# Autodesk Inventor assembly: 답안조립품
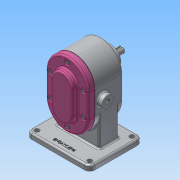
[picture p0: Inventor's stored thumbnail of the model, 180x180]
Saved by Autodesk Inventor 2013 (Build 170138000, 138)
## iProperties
Created: 2020-09
Part Number: 답안조립품
Document SubType Name: Assembly
Designer: Administrator
Author: Administrator
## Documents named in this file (11)
- C:\Users\Administrator\Desktop\700906V1002\답안조립품.iam
- C:\Users\Administrator\Desktop\700906V1002\본체.ipt
- C:\Users\Administrator\Desktop\700906V1002\메인축.ipt
- C:\Users\Administrator\Desktop\700906V1002\베어링부시.ipt
- C:\Users\Administrator\Desktop\700906V1002\스퍼기어.ipt
- C:\Users\Administrator\Desktop\700906V1002\개스킷.ipt
- C:\Users\Administrator\Desktop\700906V1002\키 6 x 6 x 18.ipt
- C:\Users\Administrator\Desktop\700906V1002\커버.ipt
- C:\Users\Administrator\Desktop\700906V1002\서브축.ipt
- C:\Users\Administrator\Desktop\700906V1002\볼트 M5.ipt
- C:\Users\Administrator\Desktop\700906V1002\오일 실 16 28 7.ipt
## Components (1 placed, 1 different names)
1. 개스킷:1
